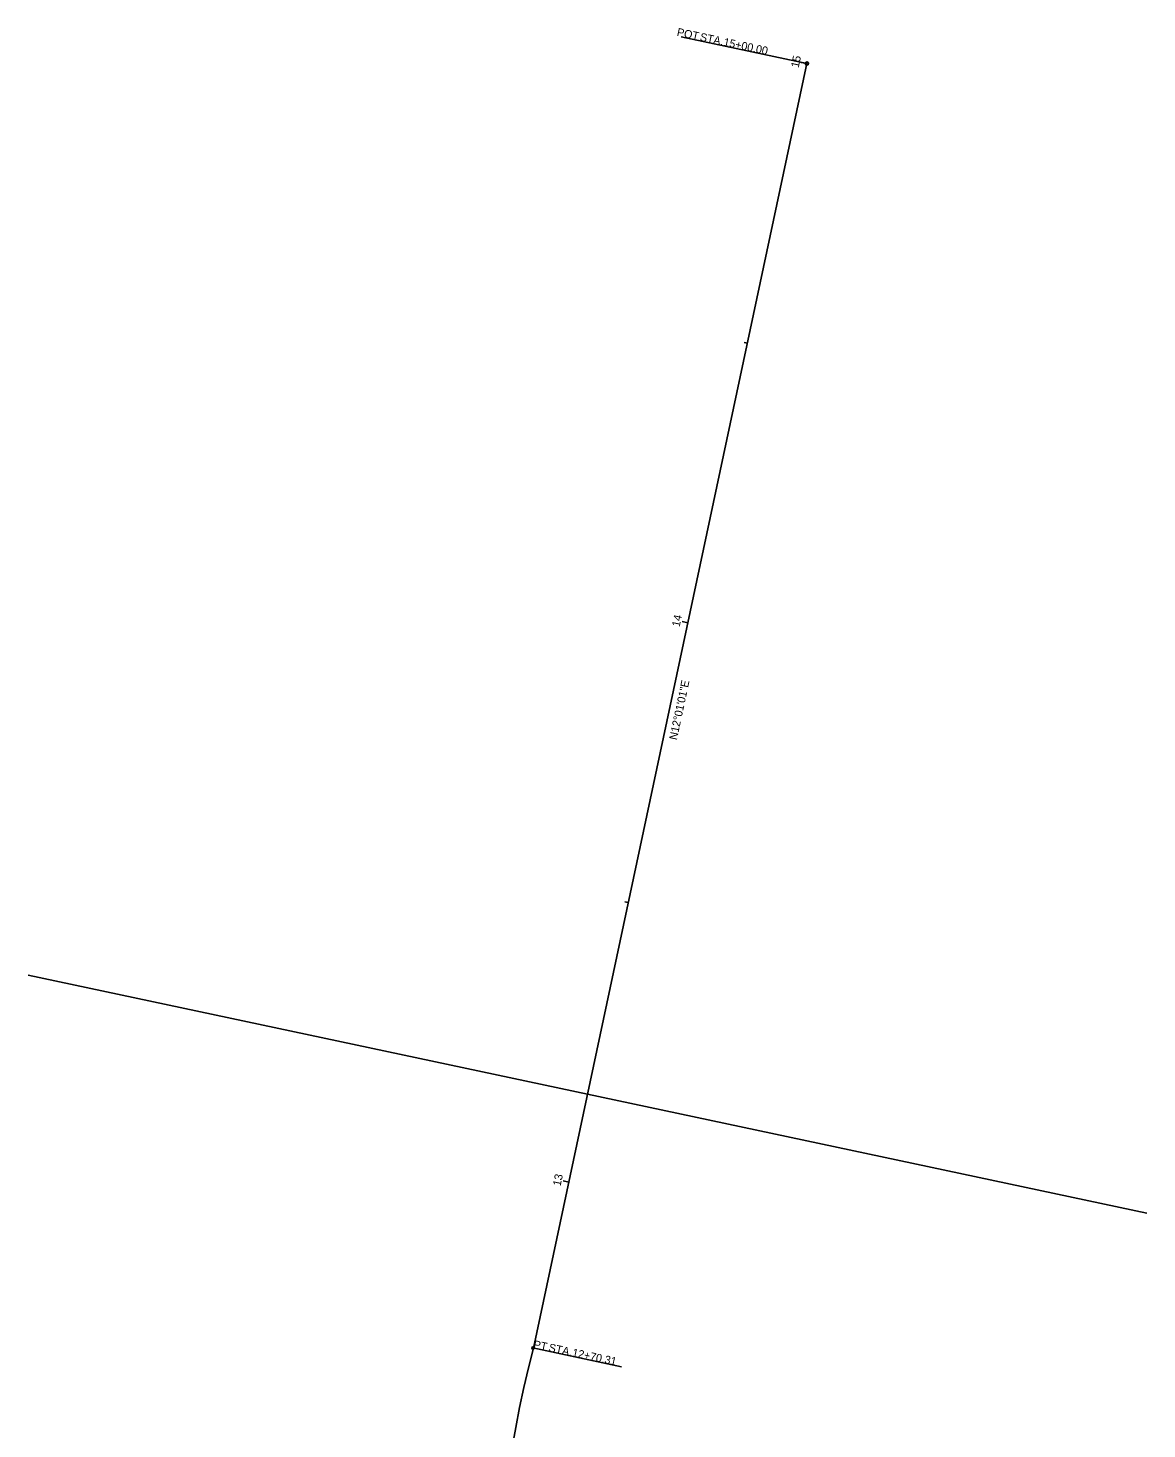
# Model space of a CAD drawing. Extents: x 2296330 to 2296526, y 654819 to 655309.
# Drawn here: x 2296329.9 to 2296525.5, y 655064.1 to 655309.1 of the extents above; entities that cross this region are included whole.
import ezdxf

# ---------------------------------------------------------------- set-up
doc = ezdxf.new("R2010")
doc.units = 0
for name, color, linetype in [('BR_P_Gen_Centerline', 7, 'Continuous'), ('Default', 7, 'Continuous'), ('GE_P_Alignment', 7, 'Continuous'), ('GE_P_Alignment_100_Bearings', 7, 'Continuous'), ('GE_P_Alignment_100_Cardinal_Points', 7, 'Continuous'), ('GE_P_Alignment_100_Stations', 7, 'Continuous')]:
    doc.layers.add(name, color=color, linetype=linetype)

msp = doc.modelspace()

# ---------------------------------------------------------------- linework, layer by layer
at = {"layer": 'BR_P_Gen_Centerline'}
msp.add_line((2296329.91, 655143.47), (2296525.53, 655101.83), dxfattribs=at)
at = {"layer": 'Default'}
for p, q in [((2296422.51, 655098.16), (2296422.51, 655098.2)), ((2296422.51, 655098.2), (2296422.51, 655098.19))]:
    msp.add_line(p, q, dxfattribs=at)
at = {"layer": 'GE_P_Alignment'}
msp.add_line((2296418.26, 655078.22), (2296466.08, 655302.88), dxfattribs=at)
msp.add_line((2296418.26, 655078.22), (2296466.08, 655302.88), dxfattribs=at)
msp.add_arc((2296640.37, 655021.32), 229.28, 165.6301, 221.5381, dxfattribs=at)
msp.add_arc((2296640.37, 655021.32), 229.28, 165.6301, 221.5381, dxfattribs=at)
at = {"layer": 'GE_P_Alignment_100_Cardinal_Points'}
for p, q in [((2296466.08, 655302.88), (2296444.08, 655307.56)), ((2296418.17, 655078.24), (2296433.65, 655074.94))]:
    msp.add_line(p, q, dxfattribs=at)
for centre, radius in [((2296466.08, 655302.88), 0.3), ((2296418.17, 655078.24), 0.211)]:
    msp.add_circle(centre, radius, dxfattribs=at)
at = {"layer": 'GE_P_Alignment_100_Stations'}
for p, q in [((2296466.08, 655302.88), (2296465.1, 655303.09)), ((2296455.67, 655253.97), (2296455.09, 655254.1)), ((2296445.26, 655205.07), (2296444.28, 655205.28)), ((2296434.85, 655156.17), (2296434.27, 655156.29)), ((2296424.44, 655107.26), (2296423.46, 655107.47))]:
    msp.add_line(p, q, dxfattribs=at)

# ---------------------------------------------------------------- texts
at = {"layer": 'GE_P_Alignment_100_Bearings'}
msp.add_text('N12°01\'01"E', height=1.4, rotation=77.983, dxfattribs=at).set_placement((2296443.34, 655184.49))
at = {"layer": 'GE_P_Alignment_100_Cardinal_Points'}
for s, p in [('POT', (2296443.26, 655307.76)), (' STA. ', (2296446.78, 655307.01)), ('15+00.00', (2296451.4, 655306.02)), ('PT', (2296418.17, 655078.24)), (' STA. ', (2296420.33, 655077.78)), ('12+70.31', (2296424.95, 655076.8))]:
    msp.add_text(s, height=1.4, rotation=347.983, dxfattribs=at).set_placement(p)
at = {"layer": 'GE_P_Alignment_100_Stations'}
for s, p in [('15', (2296464.63, 655302.07)), ('14', (2296443.82, 655204.28)), ('13', (2296423, 655106.47))]:
    msp.add_text(s, height=1.4, rotation=77.983, dxfattribs=at).set_placement(p)

doc.saveas('drawing.dxf')
